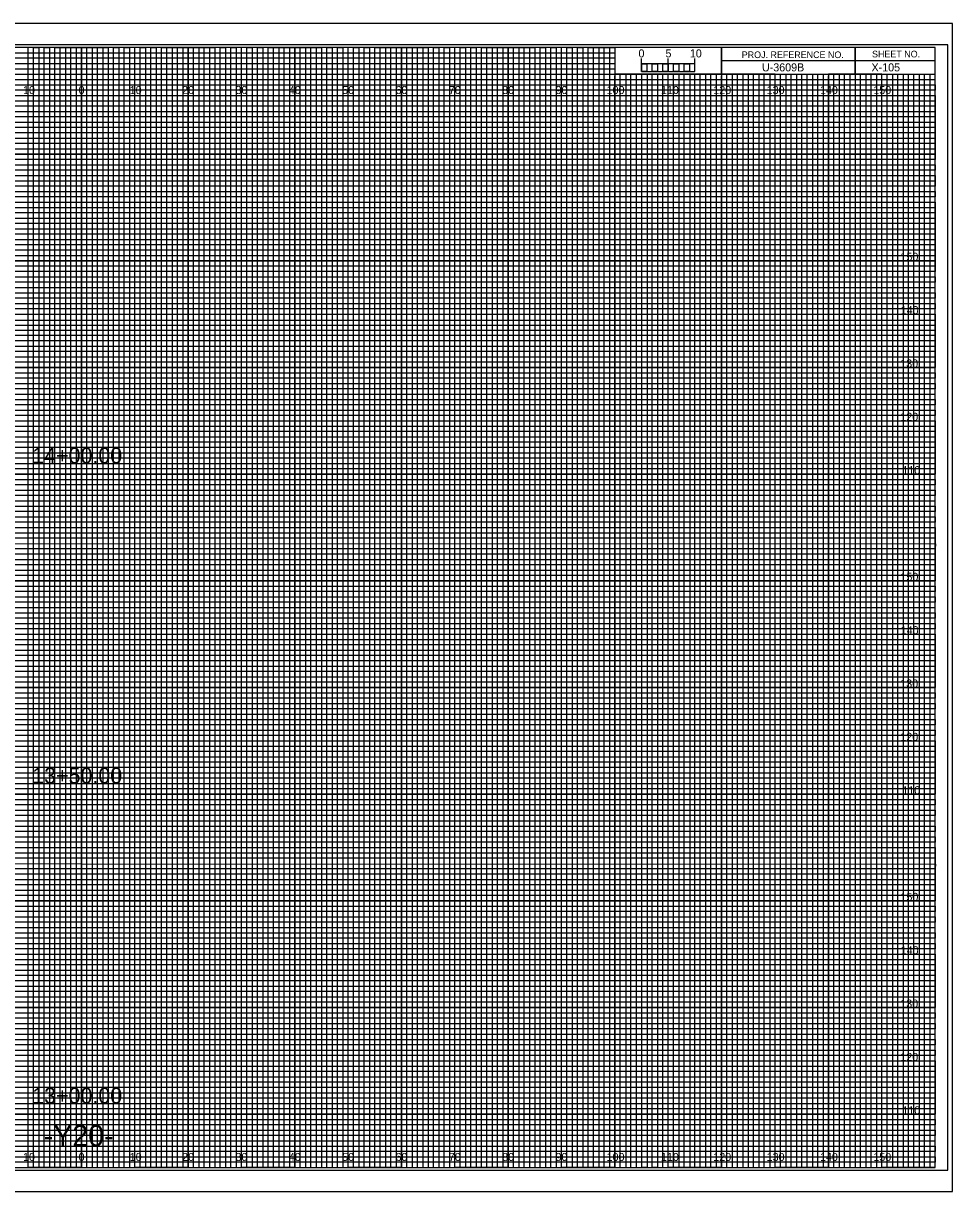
# Model space of a CAD drawing. Extents: x -13 to 323, y -5 to 2634.
# Drawn here: x 149.1 to 323.3, y 435.5 to 654.5 of the extents above; entities that cross this region are included whole.
import ezdxf

# ---------------------------------------------------------------- set-up
doc = ezdxf.new("R2010")
doc.units = 0
for name, color, linetype in [('Exist CMT Pavement', 7, 'Continuous'), ('Exist Cross Section Cell', 7, 'Continuous'), ('Exist XS Center Line Elevation Label', 7, 'Continuous'), ('Exist XS Ground Line', 7, 'Continuous'), ('Prop CMT Pvmt Course 1 Wedge', 7, 'Continuous'), ('Prop CMT Pvmt Course 2', 7, 'Continuous'), ('Prop CMT Pvmt Course 2 Wedge', 7, 'Continuous'), ('Prop CMT Pvmt Course 3', 7, 'Continuous'), ('Prop CMT Pvmt Course 3 Wedge', 7, 'Continuous'), ('Prop CMT Pvmt Surface', 7, 'Continuous'), ('Prop CMT Pvmt Wedge Surface 1', 7, 'Continuous'), ('Prop CMT Pvmt Wedge Surface 2', 7, 'Continuous'), ('Prop CMT Shld Paved Course 1', 7, 'Continuous'), ('Prop CMT Shld Paved Course 2', 7, 'Continuous'), ('Prop CMT Shld Paved Course 3', 7, 'Continuous'), ('Prop CMT Subgrade Earthwork', 7, 'Continuous'), ('Scratch_Level_0', 7, 'Continuous')]:
    doc.layers.add(name, color=color, linetype=linetype)

msp = doc.modelspace()

# ---------------------------------------------------------------- linework, layer by layer
at = {"layer": 'Exist XS Center Line Elevation Label'}
for points in [[(145, 440), (155, 440), (155, 650), (165, 650), (165, 440), (175, 440), (175, 650), (185, 650), (185, 440), (195, 440), (195, 650), (205, 650), (205, 440), (215, 440), (215, 650), (225, 650), (225, 440), (235, 440), (235, 650), (245, 650), (245, 440), (255, 440), (255, 650), (259.93, 650), (260, 650), (260, 645), (264.99, 645), (264.99, 440), (275, 440), (275, 645), (285, 645), (285, 440), (295, 440), (295, 645), (305, 645), (305, 440), (315, 440), (315, 645)], [(0, 645), (275, 645)], [(0, 625), (320, 625), (320, 635), (0, 635)], [(0, 605), (320, 605), (320, 615), (0, 615)], [(0, 585), (320, 585), (320, 595), (0, 595)], [(0, 565), (320, 565), (320, 575), (0, 575)], [(0, 545), (320, 545), (320, 555), (0, 555)], [(0, 525), (320, 525), (320, 535), (0, 535)], [(0, 505), (320, 505), (320, 515), (0, 515)], [(0, 485), (320, 485), (320, 495), (0, 495)], [(0, 465), (320, 465), (320, 475), (0, 475)], [(0, 445), (320, 445), (320, 455), (0, 455)]]:
    msp.add_lwpolyline(points, dxfattribs=at)
at = {"layer": 'Exist XS Ground Line'}
for p, q in [((150, 650), (140, 650)), ((150, 440), (150, 650)), ((170, 650), (160, 650)), ((160, 650), (160, 440)), ((170, 440), (170, 650)), ((190, 650), (180, 650)), ((180, 650), (180, 440)), ((190, 440), (190, 650)), ((210, 650), (200, 650)), ((200, 650), (200, 440)), ((210, 440), (210, 650)), ((230, 650), (220, 650)), ((220, 650), (220, 440)), ((230, 440), (230, 650)), ((250, 650), (240, 650)), ((240, 650), (240, 440)), ((250, 440), (250, 650)), ((260, 650), (260, 440)), ((270, 440), (270, 645)), ((290, 645), (280, 645)), ((280, 645), (280, 440)), ((290, 440), (290, 645)), ((310, 645), (300, 645)), ((300, 645), (300, 440)), ((310, 440), (310, 645)), ((160, 440), (150, 440)), ((180, 440), (170, 440)), ((200, 440), (190, 440)), ((220, 440), (210, 440)), ((240, 440), (230, 440)), ((260, 440), (250, 440)), ((280, 440), (270, 440)), ((300, 440), (290, 440)), ((320, 440), (310, 440)), ((320, 440), (320, 440))]:
    msp.add_line(p, q, dxfattribs=at)
for points in [[(0, 640), (320, 640), (320, 630), (0, 630)], [(0, 620), (320, 620), (320, 610), (0, 610)], [(0, 600), (320, 600), (320, 590), (0, 590)], [(0, 580), (320, 580), (320, 570), (0, 570)], [(0, 560), (320, 560), (320, 550), (0, 550)], [(0, 540), (320, 540), (320, 530), (0, 530)], [(0, 520), (320, 520), (320, 510), (0, 510)], [(0, 500), (320, 500), (320, 490), (0, 490)], [(0, 480), (320, 480), (320, 470), (0, 470)], [(0, 460), (320, 460), (320, 450), (0, 450)]]:
    msp.add_lwpolyline(points, dxfattribs=at)
at = {"layer": 'Prop CMT Pvmt Course 1 Wedge'}
for p, q in [((323.3, 654.5), (-13.4, 654.5)), ((-13.4, 435.5), (323.3, 435.5))]:
    msp.add_line(p, q, dxfattribs=at)
at = {"layer": 'Prop CMT Pvmt Course 2'}
msp.add_lwpolyline([(-13.4, 435.5), (323.3, 435.5), (323.3, 654.5), (-13.4, 654.5)], close=True, dxfattribs=at)
at = {"layer": 'Prop CMT Pvmt Course 3'}
msp.add_lwpolyline([(-10.8, 439.5), (322.4, 439.5), (322.4, 650.5), (-10.8, 650.5)], close=True, dxfattribs=at)
at = {"layer": 'Prop CMT Shld Paved Course 1'}
for p, q in [((305, 650), (305, 645)), ((305, 645), (305, 650)), ((280, 647.5), (280, 645)), ((320, 647.49), (280, 647.49)), ((280, 645), (320, 645))]:
    msp.add_line(p, q, dxfattribs=at)
for points in [[(320, 650), (0, 650), (0, 440), (320, 440)], [(280, 650), (260, 650), (260, 645.03), (280, 645.03)], [(320, 650), (280, 650), (280, 645), (320, 645)]]:
    msp.add_lwpolyline(points, close=True, dxfattribs=at)
at = {"layer": 'Prop CMT Shld Paved Course 2'}
for p, q in [((267, 645), (266.01, 645)), ((266.01, 645), (266.01, 440)), ((267, 440), (267, 645)), ((269, 645), (268, 645)), ((268, 645), (268, 440)), ((269, 440), (269, 645)), ((266.01, 440), (265, 440)), ((268, 440), (267, 440))]:
    msp.add_line(p, q, dxfattribs=at)
for points in [[(150, 440), (151, 440), (151, 650), (152, 650), (152, 440)], [(152, 440), (153, 440), (153, 650), (154, 650), (154, 440)], [(155, 440), (156, 440), (156, 650), (157, 650), (157, 440)], [(157, 440), (158, 440), (158, 650), (159, 650), (159, 440)], [(160, 440), (161, 440), (161, 650), (162, 650), (162, 440)], [(162, 440), (163, 440), (163, 650), (164, 650), (164, 440)], [(165, 440), (166, 440), (166, 650), (167, 650), (167, 440)], [(167, 440), (168, 440), (168, 650), (169, 650), (169, 440)], [(170, 440), (171, 440), (171, 650), (172, 650), (172, 440)], [(172, 440), (173, 440), (173, 650), (174, 650), (174, 440)], [(175, 440), (176, 440), (176, 650), (177, 650), (177, 440)], [(177, 440), (178, 440), (178, 650), (179, 650), (179, 440)], [(180, 440), (181, 440), (181, 650), (182, 650), (182, 440)], [(182, 440), (183, 440), (183, 650), (184, 650), (184, 440)], [(185, 440), (186, 440), (186, 650), (187, 650), (187, 440)], [(187, 440), (188, 440), (188, 650), (189, 650), (189, 440)], [(190, 440), (191, 440), (191, 650), (192, 650), (192, 440)], [(192, 440), (193, 440), (193, 650), (194, 650), (194, 440)], [(195, 440), (196, 440), (196, 650), (197, 650), (197, 440)], [(197, 440), (198, 440), (198, 650), (199, 650), (199, 440)], [(200, 440), (201, 440), (201, 650), (202, 650), (202, 440)], [(202, 440), (203, 440), (203, 650), (204, 650), (204, 440)], [(205, 440), (206, 440), (206, 650), (207, 650), (207, 440)], [(207, 440), (208, 440), (208, 650), (209, 650), (209, 440)], [(210, 440), (211, 440), (211, 650), (212, 650), (212, 440)], [(212, 440), (213, 440), (213, 650), (214, 650), (214, 440)], [(215, 440), (216, 440), (216, 650), (217, 650), (217, 440)], [(217, 440), (218, 440), (218, 650), (219, 650), (219, 440)], [(220, 440), (221, 440), (221, 650), (222, 650), (222, 440)], [(222, 440), (223, 440), (223, 650), (224, 650), (224, 440)], [(225, 440), (226, 440), (226, 650), (227, 650), (227, 440)], [(227, 440), (228, 440), (228, 650), (229, 650), (229, 440)], [(230, 440), (231, 440), (231, 650), (232, 650), (232, 440)], [(232, 440), (233, 440), (233, 650), (234, 650), (234, 440)], [(235, 440), (236, 440), (236, 650), (237, 650), (237, 440)], [(237, 440), (238, 440), (238, 650), (239, 650), (239, 440)], [(240, 440), (241, 440), (241, 650), (242, 650), (242, 440)], [(242, 440), (243, 440), (243, 650), (244, 650), (244, 440)], [(245, 440), (246, 440), (246, 650), (247, 650), (247, 440)], [(247, 440), (248, 440), (248, 650), (249, 650), (249, 440)], [(250, 440), (251, 440), (251, 650), (252, 650), (252, 440)], [(252, 440), (253, 440), (253, 650), (254, 650), (254, 440)], [(255, 440), (256, 440), (256, 650), (257, 650), (257, 440)], [(257, 440), (258, 440), (258, 650), (259, 650), (259, 440)], [(260, 440), (261, 440), (261, 645), (262.02, 645), (262.02, 440)], [(262, 440), (263, 440), (263, 645), (263.99, 645), (263.99, 440)], [(270, 440), (270.98, 440), (270.98, 645), (272, 645), (272, 440)], [(272, 440), (273, 440), (273, 645), (274.05, 645), (274.05, 440)], [(275, 440), (276, 440), (276, 645), (277, 645), (277, 440)], [(277, 440), (278, 440), (278, 645), (279, 645), (279, 440)], [(280, 440), (281, 440), (281, 645), (282, 645), (282, 440)], [(282, 440), (283, 440), (283, 645), (284, 645), (284, 440)], [(285, 440), (286, 440), (286, 645), (287, 645), (287, 440)], [(287, 440), (288, 440), (288, 645), (289, 645), (289, 440)], [(290, 440), (291, 440), (291, 645), (292, 645), (292, 440)], [(292, 440), (293, 440), (293, 645), (294, 645), (294, 440)], [(295, 440), (296, 440), (296, 645), (297, 645), (297, 440)], [(297, 440), (298, 440), (298, 645), (299, 645), (299, 440)], [(300, 440), (301, 440), (301, 645), (302, 645), (302, 440)], [(302, 440), (303, 440), (303, 645), (304, 645), (304, 440)], [(305, 440), (306, 440), (306, 645), (307, 645), (307, 440)], [(307, 440), (308, 440), (308, 645), (309, 645), (309, 440)], [(310, 440), (311, 440), (311, 645), (312, 645), (312, 440)], [(312, 440), (313, 440), (313, 645), (314, 645), (314, 440)], [(315, 440), (316, 440), (316, 645), (317, 645), (317, 440)], [(317, 440), (318, 440), (318, 645), (319, 645), (319, 440)]]:
    msp.add_lwpolyline(points, dxfattribs=at)
at = {"layer": 'Prop CMT Shld Paved Course 3'}
for p, q in [((265, 645.49), (265, 647.9)), ((265, 646.9), (265, 647.9)), ((270, 645.49), (270, 647.9)), ((275, 645.49), (275, 647.9)), ((275, 646.9), (275, 647.9))]:
    msp.add_line(p, q, dxfattribs=at)
for points in [[(275, 646.9), (265, 646.9), (265, 645.49), (275, 645.49)], [(265, 646.9), (266, 646.9), (266, 645.49), (265, 645.49)], [(267, 646.9), (268, 646.9), (268, 645.49), (267, 645.49)], [(269, 646.9), (270, 646.9), (270, 645.49), (269, 645.49)], [(271, 646.9), (272, 646.9), (272, 645.49), (271, 645.49)], [(273, 646.9), (274, 646.9), (274, 645.49), (273, 645.49)]]:
    msp.add_lwpolyline(points, close=True, dxfattribs=at)
at = {"layer": 'Prop CMT Subgrade Earthwork'}
for p, q in [((150, 440), (150, 650)), ((160, 440), (160, 650)), ((170, 440), (170, 650)), ((180, 440), (180, 650)), ((190, 440), (190, 650)), ((200, 440), (200, 650)), ((210, 440), (210, 650)), ((220, 440), (220, 650)), ((230, 440), (230, 650)), ((240, 440), (240, 650)), ((250, 440), (250, 650)), ((260, 440), (260, 644.69)), ((270, 440), (270, 644.69)), ((280, 440), (280, 644.69)), ((290, 440), (290, 644.69)), ((300, 440), (300, 644.69)), ((310, 440), (310, 644.69)), ((0, 640), (320, 640)), ((0, 630), (320, 630)), ((0, 620), (320, 620)), ((0, 610), (320, 610)), ((0, 600), (320, 600)), ((0, 590), (320, 590)), ((0, 580), (320, 580)), ((0, 570), (320, 570)), ((0, 560), (320, 560)), ((0, 550), (320, 550)), ((0, 540), (320, 540)), ((0, 530), (320, 530)), ((0, 520), (320, 520)), ((0, 510), (320, 510)), ((0, 500), (320, 500)), ((0, 490), (320, 490)), ((0, 480), (320, 480)), ((0, 470), (320, 470)), ((0, 460), (320, 460)), ((0, 450), (320, 450))]:
    msp.add_line(p, q, dxfattribs=at)
at = {"layer": 'Scratch_Level_0'}
for p, q in [((0, 649), (260, 649)), ((260, 649), (260, 647.98)), ((260, 647.98), (0, 647.98)), ((0, 647), (260, 647)), ((260, 647), (260, 645.89)), ((260, 645.89), (0, 645.89)), ((0, 644), (320, 644))]:
    msp.add_line(p, q, dxfattribs=at)
for points in [[(0, 643), (270, 643), (320, 643), (320, 642), (0, 642)], [(0, 641), (320, 641), (320, 639), (0, 639)], [(0, 638), (320, 638), (320, 637), (0, 636.98)], [(0, 636), (320, 636), (320, 634), (0, 634)], [(0, 633), (320, 633), (320, 632), (0, 632)], [(0, 631), (320, 631), (320, 629), (0, 629)], [(0, 628), (320, 628), (320, 627), (0, 627)], [(0, 626), (320, 626), (320, 624), (0, 624)], [(0, 623), (320, 623), (320, 622), (0, 622)], [(0, 621), (320, 621), (320, 619), (0, 619)], [(0, 618), (320, 618), (320, 617), (0, 617)], [(0, 616), (320, 616), (320, 613.95), (320, 613), (320, 612), (0, 612)], [(0, 614), (320, 614), (320, 613), (0, 613)], [(0, 611), (320, 611), (320, 609), (0, 609.03)], [(0, 609.03), (320, 609), (320, 608), (0, 608)], [(0, 607), (320, 607), (320, 606), (0, 606)], [(0, 604), (320, 604), (320, 603), (0, 603)], [(0, 602), (320, 602), (320, 601), (0, 601)], [(-0.07, 598.89), (320, 598.89), (320, 597.88), (-0.07, 597.88)], [(0, 597), (320, 597), (320, 596), (0, 596)], [(0, 594), (320, 594), (320, 593), (0, 593)], [(0, 592), (320, 592), (320, 591), (0, 591)], [(0, 589), (320, 589), (320, 588), (0, 588)], [(0, 587), (320, 587), (320, 586), (0, 586)], [(0, 584), (320, 584), (320, 583), (0, 583)], [(0, 582), (320, 582), (320, 581), (0, 581)], [(0, 579), (320, 579), (319.99, 577.98), (0, 578)], [(0, 577), (320, 577), (320, 576), (0, 576)], [(0, 574), (320, 574), (320, 573), (0, 573)], [(0, 572), (320, 572), (320, 571), (0, 571)], [(0, 569), (320, 569), (320, 568), (0, 568)], [(0, 567), (320, 567), (320, 566), (0, 566)], [(0, 564), (320, 564), (320, 563), (0, 563)], [(0, 562), (320, 562), (320, 561), (0, 561)], [(0, 559), (320, 559), (320, 558), (0, 558)], [(0, 556.99), (320.07, 556.91), (320, 556), (0, 556)], [(0, 554), (320, 554), (320, 553), (0, 553)], [(0, 552), (320, 552), (320, 551), (0, 551)], [(0, 549), (320, 549), (320, 548), (0, 548)], [(0, 547), (320, 547), (320, 546), (0, 546)], [(0, 544), (320, 544), (320, 543), (0, 543)], [(0, 542), (320, 542), (320, 541), (0, 541)], [(0, 539), (320, 539), (320, 538), (0, 538)], [(0, 537), (320, 537), (320, 536), (0, 536)], [(0, 534), (320, 534), (320, 533), (0, 533)], [(0, 532), (320, 532), (320, 531), (0, 531)], [(0, 529), (320, 529), (320, 528), (0, 528)], [(0, 527), (320, 527), (320, 526), (0, 526)], [(0, 524), (320, 524), (320, 523), (0, 523)], [(0, 522), (320, 522), (320, 521), (0, 521)], [(0, 519), (320, 519), (319.99, 517.98), (0, 518)], [(0, 517), (320, 517), (320, 516), (0, 516)], [(0, 514), (320, 514), (320, 513), (0, 513)], [(0, 512), (320, 512), (320, 511), (0, 511)], [(0, 509), (320, 509), (320, 508), (0, 508)], [(0, 507), (320, 507), (320, 506), (0, 506)], [(0, 504), (320, 504), (320, 503), (0, 503)], [(0, 502), (320, 502), (320, 501), (0, 501)], [(0, 499), (320, 499), (320, 498), (0, 498)], [(0, 496.99), (320.07, 496.91), (320, 496), (0, 496)], [(0, 494), (320, 494), (320, 493), (0, 493)], [(0, 492), (320, 492), (320, 491), (0, 491)], [(0, 489), (320, 489), (320, 488), (0, 488)], [(0, 487), (320, 487), (320, 486), (0, 486)], [(0, 484), (320, 484), (320, 483), (0, 483)], [(0, 482), (320, 482), (320, 481), (0, 481)], [(0, 479), (320, 479), (320, 478), (0, 478)], [(0, 477), (320, 477), (320, 476), (0, 476)], [(0, 474), (320, 474), (320, 473), (0, 473)], [(0, 472), (320, 472), (320, 471), (0, 471)], [(0, 469), (320, 469), (320, 468), (0, 468)], [(0, 467), (320, 467), (320, 466), (0, 466)], [(0, 464), (320, 464), (320, 463), (0, 463)], [(0, 462), (320, 462), (320, 461), (0, 461)], [(0, 459), (320, 459), (320, 458), (0, 458)], [(0, 457), (320, 457), (320, 456), (0, 456)], [(0, 454), (320, 454), (320, 453), (0, 453)], [(0, 452), (320, 452), (320, 451), (0, 451)], [(0, 449), (320, 449), (320, 448), (0, 448)], [(0, 447), (320, 447), (320, 446), (0, 446)], [(0, 444), (320, 444), (320, 443), (0, 443)], [(0, 442), (320, 442), (320, 441), (0, 441)]]:
    msp.add_lwpolyline(points, dxfattribs=at)

# ---------------------------------------------------------------- texts
at = {"layer": 'Exist CMT Pavement'}
msp.add_text('X-105', height=1.5, dxfattribs=at).set_placement((308.09, 645.5))
at = {"layer": 'Exist Cross Section Cell'}
for s, p in [('10', (149.04, 641.25)), ('0', (159.45, 641.25)), ('0', (159.45, 641.25)), ('10', (169.04, 641.25)), ('20', (178.86, 641.25)), ('30', (188.86, 641.25)), ('40', (198.86, 641.25)), ('50', (208.86, 641.25)), ('60', (218.86, 641.25)), ('70', (228.86, 641.25)), ('80', (238.86, 641.25)), ('90', (248.86, 641.25)), ('100', (258.44, 641.25)), ('110', (268.62, 641.25)), ('120', (278.44, 641.25)), ('130', (288.44, 641.25)), ('140', (298.44, 641.25)), ('150', (308.44, 641.25)), ('10', (149.04, 441.25)), ('0', (159.45, 441.25)), ('0', (159.45, 441.25)), ('10', (169.04, 441.25)), ('20', (178.86, 441.25)), ('30', (188.86, 441.25)), ('40', (198.86, 441.25)), ('50', (208.86, 441.25)), ('60', (218.86, 441.25)), ('70', (228.86, 441.25)), ('80', (238.86, 441.25)), ('90', (248.86, 441.25)), ('100', (258.44, 441.25)), ('110', (268.62, 441.25)), ('120', (278.44, 441.25)), ('130', (288.44, 441.25)), ('140', (298.44, 441.25)), ('150', (308.44, 441.25))]:
    msp.add_text(s, height=1.5, dxfattribs=at).set_placement(p)
at = {"layer": 'Prop CMT Pvmt Course 2 Wedge'}
for s, p in [('150', (313.52, 610)), ('140', (313.57, 600)), ('130', (313.49, 590)), ('120', (313.5, 580)), ('110', (313.88, 570)), ('150', (313.52, 550)), ('140', (313.57, 540)), ('130', (313.49, 530)), ('120', (313.5, 520)), ('110', (313.88, 510)), ('150', (313.52, 490)), ('140', (313.57, 480)), ('130', (313.49, 470)), ('120', (313.5, 460)), ('110', (313.88, 450))]:
    msp.add_text(s, height=1.5, dxfattribs=at).set_placement(p)
at = {"layer": 'Prop CMT Pvmt Course 3 Wedge'}
for s, p in [('14+00.00', (150.77, 572)), ('13+50.00', (150.77, 512)), ('13+00.00', (150.77, 452))]:
    msp.add_text(s, height=3, dxfattribs=at).set_placement(p)
at = {"layer": 'Prop CMT Pvmt Surface'}
msp.add_text('U-3609B', height=1.5, dxfattribs=at).set_placement((287.56, 645.5))
at = {"layer": 'Prop CMT Pvmt Wedge Surface 1'}
msp.add_text('-Y20-', height=4, dxfattribs=at).set_placement((152.93, 444))
at = {"layer": 'Prop CMT Pvmt Wedge Surface 2'}
for s, p in [('5', (269.47, 648.12)), ('10', (274.04, 648.12))]:
    msp.add_text(s, height=1.5, dxfattribs=at).set_placement(p)
at = {"layer": 'Prop CMT Shld Paved Course 1'}
for s, p in [('PROJ. REFERENCE NO.', (283.77, 647.99)), ('SHEET NO.', (308.19, 648.12))]:
    msp.add_text(s, height=1.25, dxfattribs=at).set_placement(p)
at = {"layer": 'Prop CMT Shld Paved Course 3'}
msp.add_text('0', height=1.5, dxfattribs=at).set_placement((264.41, 648.12))

doc.saveas('drawing.dxf')
